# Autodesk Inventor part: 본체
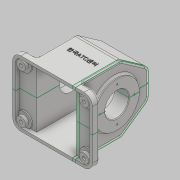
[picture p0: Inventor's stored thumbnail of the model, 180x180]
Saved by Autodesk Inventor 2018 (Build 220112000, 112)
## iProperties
Created: 2022-12
Part Number: 본체
Material: 일반
Document SubType Name: Modeling
Designer: home
Density: 1 g/cm^3
Appearance: 기본값
Author: home
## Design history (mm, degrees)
sketch "스케치1"
  geometry: L1 (53, -55)-(-53, -55); L2 (-67, -41)-(-67, 41); L3 (-53, 55)-(53, 55); L4 (67, 41)-(67, -41); L5 (67, -55)-(-67, 55); L6 (-67, -55)-(67, 55); A1 r 14 centre (53, -41) between (53, -55) and (67, -41); A2 r 14 centre (-53, -41) between (-67, -41) and (-53, -55); A3 r 14 centre (-53, 41) between (-53, 55) and (-67, 41); A4 r 14 centre (53, 41) between (67, 41) and (53, 55); 1 further point
  constraints: 12 end point, 8 point on circle, 8 point on line, 8 tangent, 4 centre point, 3 equal radius, 2 midpoint, 2 parallel, 1 horizontal, 1 perpendicular
  dimensions: "d0" = 134 distance of L5.end L6.end; "d1" = 110 distance of L6.start L5.end; "d2" = 14 radius of A1
extrude "돌출1" new body sketch "스케치1" distance "d3" = 12; taper "d4" = 0 deg
sketch "스케치2"
  geometry: L1 (67, 41)-(67, -41) reference; L2 (53, -55)-(-53, -55) reference; L3 (-67, -41)-(-67, 41) reference; L4 (-53, 55)-(53, 55) reference; C1 r 7.5 at (-53, 41); C2 r 7.5 at (53, 41); C3 r 7.5 at (-53, -41); C4 r 7.5 at (53, -41); A1 r 14 centre (53, 41) between (67, 41) and (53, 55) reference; A2 r 14 centre (53, -41) between (53, -55) and (67, -41) reference; A3 r 14 centre (-53, -41) between (-67, -41) and (-53, -55) reference; A4 r 14 centre (-53, 41) between (-53, 55) and (-67, 41) reference; 1 further point
  constraints: 4 centre point, 4 coincident
  dimensions: "d5" = 15 diameter of C1; "d6" = 15 diameter of C2; "d7" = 15 diameter of C3; "d8" = 15 diameter of C4
extrude "돌출2" cut sketch "스케치2" distance "d9" = 2; taper "d10" = 0 deg
sketch "스케치3"
  geometry: L1 (120, 0)-(120, -82) reference; L2 (106, -96)-(0, -96) reference; L3 (-14, -82)-(-14, 0) reference; L4 (0, 14)-(106, 14) reference; C1 r 7.5 at (0, -82) reference; C2 r 7.5 at (0, 0) reference; C3 r 7.5 at (106, 0) reference; C4 r 7.5 at (106, -82) reference; C5 r 2.75 at (0, 0); C6 r 2.75 at (106, 0); C7 r 2.75 at (0, -82); C8 r 2.75 at (106, -82); A1 r 14 centre (106, 0) between (120, 0) and (106, 14) reference; A2 r 14 centre (106, -82) between (106, -96) and (120, -82) reference; A3 r 14 centre (0, -82) between (-14, -82) and (0, -96) reference; A4 r 14 centre (0, 0) between (0, 14) and (-14, 0) reference; 1 further point
  constraints: 4 centre point, 4 coincident
  dimensions: "d11" = 5.5 diameter of C5; "d12" = 5.5 diameter of C6; "d13" = 5.5 diameter of C7; "d14" = 5.5 diameter of C8
extrude "돌출3" cut sketch "스케치3" extent not by distance; stored distance "d15" = 2; taper "d16" = 0 deg
sketch "스케치4"
  geometry: L1 (12, -55)-(0, -55) reference; L2 (0, -55)-(0, 55) reference; L3 (0, 55)-(12, 55) reference; L4 (12, 55)-(12, -55) reference; L5 (0, 55)-(77, 55); L6 (77, 55)-(122, 23.491); L7 (122, 0)-(122, 23.491); L8 (122, 0)-(122, -23.491); L9 (77, -55)-(122, -23.491); L10 (0, -55)-(77, -55); 1 further point
  constraints: 12 end point, 1 horizontal, 1 vertical
  dimensions: "d17" = 122 distance of point (0, 0) L7.start; "d18" = 77 distance of L2.end L5.end; "d19" = 35 deg angle of L6 L5
extrude "돌출4" join sketch "스케치4" stored distance "d20" = 77; taper "d21" = 0 deg
fillet "모깎기1" dims "d22" = 10
feature "쉘1" dims "d27" = 5
sketch "스케치8"
  geometry: L1 (-18.285, 122)-(18.285, 122) reference; L2 (26.477, 117.736)-(53.192, 79.583) reference; L3 (55, 73.847)-(55, 12) reference; L4 (55, 12)-(55, 0) reference; L5 (55, 0)-(50, 0) reference; L6 (50, 0)-(50, 7) reference; L7 (50, 7)-(-50, 7) reference; L8 (-50, 7)-(-50, 0) reference; L9 (-50, 0)-(-55, 0) reference; L10 (-55, 0)-(-55, 12) reference; L11 (-55, 12)-(-55, 73.847) reference; L12 (-53.192, 79.583)-(-26.477, 117.736) reference; L13 (-55, 12)-(55, 12) reference; A1 r 10 centre (-18.285, 112) between (-18.285, 122) and (-26.477, 117.736) reference; A2 r 10 centre (18.285, 112) between (26.477, 117.736) and (18.285, 122) reference; A3 r 10 centre (45, 73.847) between (55, 73.847) and (53.192, 79.583) reference; A4 r 10 centre (-45, 73.847) between (-53.192, 79.583) and (-55, 73.847) reference; 1 further point
  node "절단 모서리 투영5"
sketch "스케치9"
  geometry: 1 further point
sketch "스케치10"
  geometry: L1 (76.477, 110.736)-(103.192, 72.583) reference; L2 (105, 66.847)-(105, -7) reference; L3 (105, -7)-(100, -7) reference; L4 (100, -7)-(100, 0) reference; L5 (100, 0)-(100, 66.847) reference; L6 (99.096, 69.715)-(72.381, 107.868) reference; L7 (68.285, 110)-(31.715, 110) reference; L8 (27.619, 107.868)-(0.904, 69.715) reference; L9 (0, 66.847)-(0, 0) reference; L10 (100, 0)-(0, 0) reference; L11 (31.715, 115)-(68.285, 115) reference; L12 (-3.192, 72.583)-(23.523, 110.736) reference; L13 (-5, -7)-(-5, 66.847) reference; L14 (0, -7)-(-5, -7) reference; L15 (0, 0)-(0, -7) reference; A1 r 10 centre (68.285, 105) between (76.477, 110.736) and (68.285, 115) reference; A2 r 10 centre (95, 66.847) between (105, 66.847) and (103.192, 72.583) reference; A3 r 5 centre (95, 66.847) between (100, 66.847) and (99.096, 69.715) reference; A4 r 5 centre (68.285, 105) between (72.381, 107.868) and (68.285, 110) reference; A5 r 5 centre (31.715, 105) between (31.715, 110) and (27.619, 107.868) reference; A6 r 5 centre (5, 66.847) between (0.904, 69.715) and (0, 66.847) reference; A7 r 10 centre (31.715, 105) between (31.715, 115) and (23.523, 110.736) reference; A8 r 10 centre (5, 66.847) between (-3.192, 72.583) and (-5, 66.847) reference; 1 further point
  node "절단 모서리 투영6"
node "작업 평면1"
sketch "스케치12"
  geometry: 1 further point
sketch "스케치13"
  geometry: L1 (-18.285, 122)-(18.285, 122) reference; L2 (26.477, 117.736)-(53.192, 79.583) reference; L3 (55, 73.847)-(55, 12) reference; L4 (55, 12)-(55, 0) reference; L5 (55, 0)-(50, 0) reference; L6 (50, 0)-(50, 7) reference; L7 (50, 7)-(-50, 7) reference; L8 (-50, 7)-(-50, 0) reference; L9 (-50, 0)-(-55, 0) reference; L10 (-55, 0)-(-55, 12) reference; L11 (-55, 12)-(-55, 73.847) reference; L12 (-53.192, 79.583)-(-26.477, 117.736) reference; L13 (-55, 12)-(55, 12) reference; L14 (0, 0)-(0, 65); C1 r 37.5 at (0, 65); A1 r 10 centre (-18.285, 112) between (-18.285, 122) and (-26.477, 117.736) reference; A2 r 10 centre (18.285, 112) between (26.477, 117.736) and (18.285, 122) reference; A3 r 10 centre (45, 73.847) between (55, 73.847) and (53.192, 79.583) reference; A4 r 10 centre (-45, 73.847) between (-53.192, 79.583) and (-55, 73.847) reference
  constraints: 2 end point, 1 centre point, 1 coincident, 1 vertical
  dimensions: "d31" = 65 distance of L14.start L14.end; "d32" = 75 diameter of C1
extrude "돌출6" join sketch "스케치13" distance "d33" = 5; taper "d34" = 0 deg
sketch "스케치15"
  geometry: 1 further point
sketch "스케치16"
  geometry: L1 (26.477, 117.736)-(53.192, 79.583) reference; L2 (55, 73.847)-(55, 12) reference; L3 (55, 12)-(55, 0) reference; L4 (55, 0)-(50, 0) reference; L5 (50, 0)-(50, 7) reference; L6 (50, 7)-(-50, 7) reference; L7 (-50, 7)-(-50, 0) reference; L8 (-50, 0)-(-55, 0) reference; L9 (-55, 0)-(-55, 12) reference; L10 (-55, 12)-(-55, 73.847) reference; L11 (-53.192, 79.583)-(-26.477, 117.736) reference; L12 (-18.285, 122)-(18.285, 122) reference; L13 (-55, 12)-(55, 12) reference; L14 (0, 0)-(0, 65); C1 r 31 at (0, 65); A1 r 10 centre (18.285, 112) between (26.477, 117.736) and (18.285, 122) reference; A2 r 10 centre (45, 73.847) between (55, 73.847) and (53.192, 79.583) reference; A3 r 10 centre (-45, 73.847) between (-53.192, 79.583) and (-55, 73.847) reference; A4 r 10 centre (-18.285, 112) between (-18.285, 122) and (-26.477, 117.736) reference
  constraints: 2 end point, 1 centre point, 1 coincident, 1 vertical
  dimensions: "d39" = 65 distance of L14.start L14.end; "d40" = 62 diameter of C1
extrude "돌출8" join sketch "스케치16" distance "d41" = 10; taper "d42" = 0 deg
sketch "스케치17"
  geometry: 1 further point
sketch "스케치18"
  geometry: L1 (50, -7)-(50, 58); C1 r 37.5 at (50, 58)
  constraints: 2 end point, 1 centre point, 1 coincident, 1 vertical
  dimensions: "d43" = 65 distance of L1.start L1.end; "d45" = 75 diameter of C1
extrude "돌출9" join sketch "스케치18" distance "d46" = 14; taper "d47" = 0 deg
chamfer "모따기1" distance "d48" = 14; stored, may be unused: second distance "d49" = 2, angle "d50" = 45 deg
sketch "스케치19"
  geometry: 1 further point
hole "구멍1" diameter "d53" = 40; stored, may be unused: countersink angle "d57" = 90 deg, drill point angle "d59" = 0 deg; dims "d54" = 6.35, "d55" = 40, "d56" = 24, "d58" = 77, "d60" = 10, "d61" = 10
sketch "스케치20"
  geometry: L1 (38.5, 102.5)-(43.5, 102.5) reference; L2 (43.5, 102.5)-(43.5, 85) reference; L3 (43.5, 85)-(19.5, 85) reference; L4 (19.5, 85)-(19.5, 88.5) reference; L5 (19.5, 88.5)-(33.5, 102.5) reference; L6 (33.5, 102.5)-(33.5, 117) reference; L7 (33.5, 117)-(-33.5, 117) reference; L8 (-33.5, 117)-(-33.5, 85) reference; L9 (-33.5, 85)-(-48.5, 85) reference; L10 (-48.5, 85)-(-48.5, 96) reference; L11 (-48.5, 96)-(-38.5, 96) reference; L12 (-38.5, 96)-(-38.5, 122) reference; L13 (-38.5, 122)-(38.5, 122) reference; L14 (38.5, 122)-(38.5, 102.5) reference; L15 (-62, 7)-(-62, 0) reference; L16 (-62, 0)-(-67, 0) reference; L17 (-67, 0)-(-67, 12) reference; L18 (-67, 12)-(-38.5, 12) reference; L19 (-38.5, 12)-(-38.5, 34) reference; L20 (-38.5, 34)-(-48.5, 34) reference; L21 (-48.5, 34)-(-48.5, 45) reference; L22 (-48.5, 45)-(-33.5, 45) reference; L23 (-33.5, 45)-(-33.5, 7) reference; L24 (-33.5, 7)-(-62, 7) reference; L25 (67, 12)-(67, 0) reference; L26 (67, 0)-(62, 0) reference; L27 (62, 0)-(62, 7) reference; L28 (62, 7)-(33.5, 7) reference; L29 (33.5, 7)-(33.5, 27.5) reference; L30 (33.5, 27.5)-(19.5, 41.5) reference; L31 (19.5, 41.5)-(19.5, 45) reference; L32 (19.5, 45)-(43.5, 45) reference; L33 (43.5, 45)-(43.5, 27.5) reference; L34 (43.5, 27.5)-(38.5, 27.5) reference; L35 (38.5, 27.5)-(38.5, 12) reference; L36 (38.5, 12)-(67, 12) reference; L37 (38.5, 102.5)-(43.5, 102.5) reference; L38 (43.5, 102.5)-(43.5, 85) reference; L39 (43.5, 85)-(19.5, 85) reference; L40 (19.5, 85)-(19.5, 88.5) reference; L41 (19.5, 88.5)-(33.5, 102.5) reference; L42 (33.5, 102.5)-(33.5, 117) reference; L43 (33.5, 117)-(-33.5, 117) reference; L44 (-33.5, 117)-(-33.5, 85) reference; L45 (-33.5, 85)-(-48.5, 85) reference; L46 (-48.5, 85)-(-48.5, 96) reference; L47 (-48.5, 96)-(-38.5, 96) reference; L48 (-38.5, 96)-(-38.5, 122) reference; L49 (-38.5, 122)-(38.5, 122) reference; L50 (38.5, 122)-(38.5, 102.5) reference; L51 (-62, 7)-(-62, 0) reference; L52 (-62, 0)-(-67, 0) reference; L53 (-67, 0)-(-67, 12) reference; L54 (-67, 12)-(-38.5, 12) reference; L55 (-38.5, 12)-(-38.5, 34) reference; L56 (-38.5, 34)-(-48.5, 34) reference; L57 (-48.5, 34)-(-48.5, 45) reference; L58 (-48.5, 45)-(-33.5, 45) reference; L59 (-33.5, 45)-(-33.5, 7) reference; L60 (-33.5, 7)-(-62, 7) reference; L61 (67, 12)-(67, 0) reference; L62 (67, 0)-(62, 0) reference; L63 (62, 0)-(62, 7) reference; L64 (62, 7)-(33.5, 7) reference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; 1 further point
  node "절단 모서리 투영11"
  node "절단 모서리 투영12"
node "작업 평면2"
sketch "스케치21"
  geometry: C1 r 6 at (38.5, 18.285); 1 further point
  constraints: 1 centre point, 1 coincident
  dimensions: "d63" = 12 diameter of C1
extrude "돌출10" join sketch "스케치21" stored distance "d64" = 14; taper "d65" = 0 deg
fillet "모깎기2" dims "d66" = 3
hole "구멍2" diameter "d69" = 5.188; stored, may be unused: countersink angle "d73" = 90 deg, drill point angle "d75" = 0 deg; dims "d67" = 10, "d68" = 10, "d70" = 12, "d71" = 40, "d72" = 24, "d74" = 16
sketch "스케치22" dims "d77" = 52
  geometry: L1 (-35, -53)-(35, -53) reference; L2 (35, -53)-(35, -55) reference; L3 (35, -55)-(47, -55) reference; L4 (47, -55)-(47, -53) reference; L5 (47, -53)-(55, -53) reference; L6 (55, -53)-(55, -65) reference; L7 (55, -65)-(50, -65) reference; L8 (50, -65)-(50, -60) reference; L9 (50, -60)-(47.31, -60) reference; L10 (47.31, -60)-(47.31, -65) reference; L11 (47.31, -65)-(34.69, -65) reference; L12 (34.69, -65)-(34.69, -60) reference; L13 (34.69, -60)-(29.338, -60) reference; L14 (29.338, -60)-(29.338, -58) reference; L15 (29.338, -58)-(-29.338, -58) reference; L16 (-29.338, -58)-(-29.338, -60) reference; L17 (-29.338, -60)-(-34.69, -60) reference; L18 (-34.69, -60)-(-34.69, -65) reference; L19 (-34.69, -65)-(-47.31, -65) reference; L20 (-47.31, -65)-(-47.31, -60) reference; L21 (-47.31, -60)-(-50, -60) reference; L22 (-50, -60)-(-50, -65) reference; L23 (-50, -65)-(-55, -65) reference; L24 (-55, -65)-(-55, -53) reference; L25 (-55, -53)-(-47, -53) reference; L26 (-47, -53)-(-47, -55) reference; L27 (-47, -55)-(-35, -55) reference; L28 (-35, -55)-(-35, -53) reference; L29 (0, 0)-(0, 26); C1 r 20 at (0, 0) reference; C2 r 31 at (0, 0) reference; C3 r 20 at (0, 0) reference; 2 further points
  constraints: 2 end point, 1 coincident, 1 vertical, 1 vertical alignment, 2 other
hole "구멍3" sketch "스케치22" at (0, 26) diameter "d78" = 2.459; stored, may be unused: countersink angle "d82" = 90 deg, drill point angle "d84" = 118 deg; dims "d79" = 6, "d80" = 40, "d81" = 24, "d83" = 8.8
sketch "스케치23" dims "d88" = 58
  geometry: L1 (55, -53)-(55, -65) reference; L2 (55, -65)-(50, -65) reference; L3 (50, -65)-(50, -58) reference; L4 (50, -58)-(49.124, -58) reference; L5 (49.124, -58)-(49.124, -60) reference; L6 (49.124, -60)-(32.876, -60) reference; L7 (32.876, -60)-(32.876, -58) reference; L8 (32.876, -58)-(-32.876, -58) reference; L9 (-32.876, -58)-(-32.876, -60) reference; L10 (-32.876, -60)-(-49.124, -60) reference; L11 (-49.124, -60)-(-49.124, -58) reference; L12 (-49.124, -58)-(-50, -58) reference; L13 (-50, -58)-(-50, -65) reference; L14 (-50, -65)-(-55, -65) reference; L15 (-55, -65)-(-55, -53) reference; L16 (-55, -53)-(55, -53) reference; L17 (0, 0)-(0, 29); C1 r 20 at (0, 0) reference; C2 r 37.5 at (0, 0) reference; 1 further point
  constraints: 2 end point, 1 coincident, 1 vertical alignment, 2 other
hole "구멍4" sketch "스케치23" at (0, 29) diameter "d89" = 2.459; stored, may be unused: countersink angle "d93" = 90 deg, drill point angle "d95" = 118 deg; dims "d90" = 6, "d91" = 40, "d92" = 24, "d94" = 8.8
fillet "모깎기3" dims "d99" = 3
fillet "모깎기4" dims "d100" = 3
fillet "모깎기5" dims "d101" = 3
fillet "모깎기6" dims "d102" = 3
fillet "모깎기7" dims "d103" = 3
fillet "모깎기8" dims "d104" = 3
chamfer "모따기2" distance "d105" = 1; stored, may be unused: second distance "d106" = 2, angle "d107" = 45 deg
sketch "스케치24"
  geometry: L1 (17.5, 15)-(17.5, 73.847) reference; L2 (17.5, 73.847)-(88.5, 73.847) reference; L3 (88.5, 73.847)-(88.5, 15) reference; L4 (94.5, 9)-(106, 9) reference; L5 (106, 0)-(106, 9) reference; L6 (106, 0)-(0, 0) reference; L7 (0, 0)-(0, 9) reference; L8 (0, 9)-(11.5, 9) reference; L9 (-14.243, 0)-(14.257, 0); L10 (106, 0)-(0, 0) reference; L11 (14.257, 0)-(53.757, 0); L12 (53.757, 0)-(53.757, 50); A1 r 6 centre (94.5, 15) between (88.5, 15) and (94.5, 9) reference; A2 r 6 centre (11.5, 15) between (11.5, 9) and (17.5, 15) reference; 2 further points
  constraints: 6 end point, 2 point on line, 1 coincident, 1 perpendicular, 1 other
  dimensions: "d108" = 28.5 distance of L9.start L9.end; "d109" = 39.5 distance of L9.end L11.end; "d110" = 50 distance of L11.end L12.end
feature "엠보싱1" sketch "스케치24" dims "d111" = 0.5, "d112" = 0
sketch "스케치25"
  geometry: 1 further point
sketch "스케치26"
  geometry: 1 further point
node "솔리드1"
pattern_circular "원형 패턴1" dims angle "d86" = 360 deg
pattern_circular "원형 패턴2" dims angle "d97" = 360 deg
node "절단 모서리 투영1"
node "절단 모서리 투영2"
node "절단 모서리 투영3"
node "절단 모서리 투영8"
node "절단 모서리 투영10"
node "절단 모서리 투영13"
node "절단 모서리 투영14"
node "절단 모서리 투영15"
other parameters: "d30" = 24, "d62" = 4
